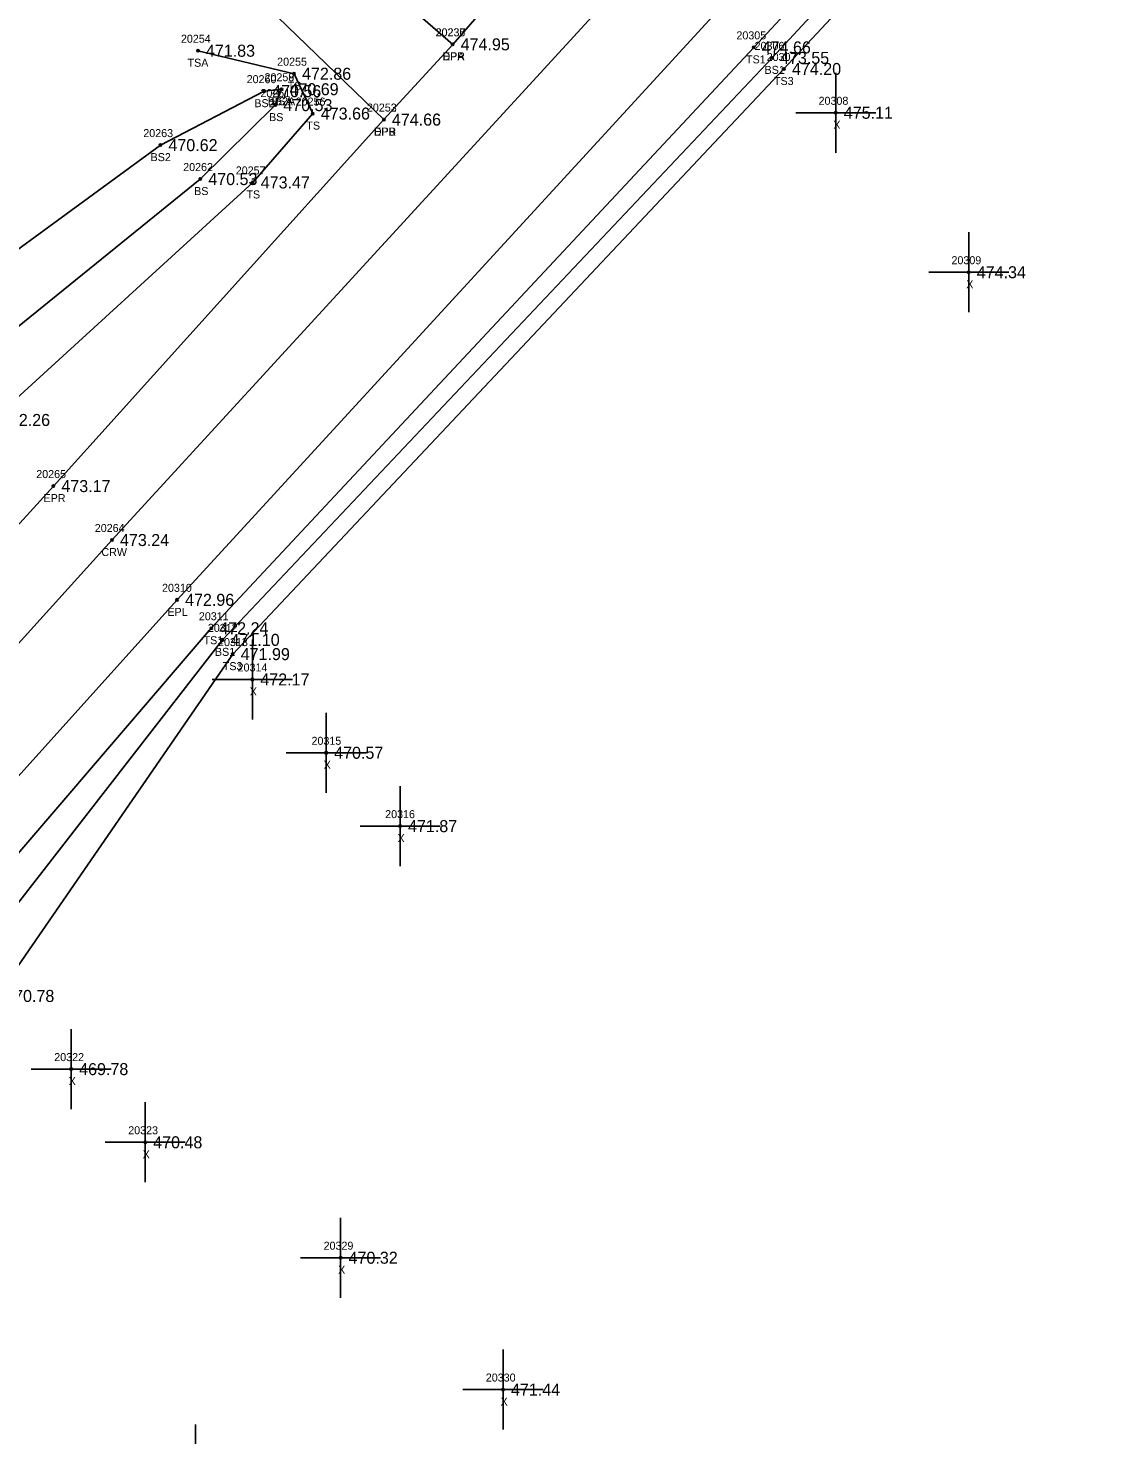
# Model space of a CAD drawing. Extents: x 1741010 to 1742139, y 749382 to 750625.
# Drawn here: x 1741665.8 to 1741801.4, y 750041.3 to 750217 of the extents above; entities that cross this region are included whole.
import ezdxf

# ---------------------------------------------------------------- set-up
doc = ezdxf.new("R2010")
doc.units = 0
for name, color, linetype in [('RD_DTM_BkLn1', 7, 'Continuous'), ('RD_DTM_BkLn2', 7, 'Continuous'), ('RD_DTM_BkLn_txCode', 7, 'Continuous'), ('RD_EX_Driveway', 7, 'Continuous'), ('RD_EX_Driveway_txCode', 7, 'Continuous'), ('RD_EX_Misc', 7, 'Continuous'), ('RD_EX_Misc_txCode', 7, 'Continuous'), ('RD_EX_Road', 7, 'Continuous'), ('RD_EX_Road_txCode', 7, 'Continuous'), ('RD_EX_TX_Driveway_ELEV', 7, 'Continuous'), ('RD_EX_TX_Misc_ELEV', 7, 'Continuous'), ('RD_EX_TX_Road_ELEV', 7, 'Continuous'), ('RD_HC_Survey_ELEV', 7, 'Continuous'), ('RD_HC_Survey_txCode', 7, 'Continuous'), ('RD_SMD_Locator', 7, 'Continuous')]:
    doc.layers.add(name, color=color, linetype=linetype)

msp = doc.modelspace()

# ---------------------------------------------------------------- linework, layer by layer
at = {"layer": 'RD_DTM_BkLn1'}
msp.add_lwpolyline([(1742095.1, 750579.47), (1742056.96, 750547.11), (1742019.74, 750514.22), (1741983.45, 750480.17), (1741948.01, 750445.01), (1741913.15, 750409.3), (1741879.03, 750372.99), (1741811.59, 750300.09), (1741743.65, 750226.52), (1741676.29, 750153.06), (1741642.32, 750115.53), (1741610.32, 750077.63)], dxfattribs=at)
at = {"layer": 'RD_DTM_BkLn2'}
for points in [[(1742105.6, 750567.48), (1742094.25, 750560.49), (1742091.64, 750555.7), (1742067.93, 750534.94), (1742031.73, 750501.95), (1741994.85, 750467.63), (1741959.82, 750432.06), (1741925.8, 750396.31), (1741891.25, 750362.62), (1741824.36, 750287.7), (1741756.44, 750214.6), (1741688.69, 750142.04), (1741655.55, 750103.43), (1741644.64, 750083.31), (1741626.06, 750060.3), (1741620, 750055.3), (1741614.97, 750059.12), (1741617.5, 750064.27), (1741619.23, 750067.96)], [(1742107.37, 750564.98), (1742099.21, 750558.66), (1742095.99, 750559.5), (1742095.15, 750554.39), (1742069.73, 750532.61), (1742034.06, 750499.81), (1741997.6, 750464.99), (1741961.88, 750429.54), (1741928.13, 750394.17), (1741895.34, 750359.02), (1741826.5, 750286.36), (1741758.73, 750213.29), (1741690.1, 750140.59), (1741658.36, 750099.77), (1741650.43, 750077.87), (1741632.9, 750061.59), (1741621.97, 750051.56), (1741618.99, 750048.78), (1741611.88, 750047.79)], [(1742108.6, 750563.87), (1742101.48, 750556.48), (1742102.57, 750548.5), (1742101.05, 750532.99), (1742105.06, 750513.92), (1742103.27, 750510.53), (1742100.54, 750509.6), (1742099.13, 750514.58), (1742095.78, 750530.6), (1742094.19, 750550.08), (1742071, 750531.59), (1742035.26, 750498.87), (1741998.91, 750463.73), (1741964.71, 750427.12), (1741930.26, 750392.09), (1741896.36, 750357.96), (1741828.15, 750284.74), (1741760.22, 750211.9), (1741691.37, 750138.81), (1741661.95, 750096.11), (1741655.14, 750072.69), (1741637.21, 750056.01), (1741627.61, 750046.43), (1741623.09, 750045.5)], [(1741687.02, 750214.18), (1741699.03, 750211.31), (1741701.37, 750206.33), (1741693.87, 750197.73), (1741661.42, 750168.06), (1741625.78, 750132.25), (1741598.95, 750108.26), (1741594.55, 750101.81), (1741595.44, 750091.73), (1741598, 750085.41), (1741619.23, 750067.96)], [(1741697.46, 750209.37), (1741696.69, 750207.39), (1741687.32, 750198.15), (1741655.45, 750172.38), (1741616.11, 750137.65), (1741593.67, 750111.75), (1741586.25, 750102.97)], [(1741697.46, 750209.37), (1741695.29, 750209.13), (1741682.34, 750202.39), (1741649.3, 750178.22), (1741602.32, 750146.46), (1741587.3, 750140.26)]]:
    msp.add_lwpolyline(points, dxfattribs=at)
at = {"layer": 'RD_EX_Driveway'}
msp.add_lwpolyline([(1741718.84, 750214.98), (1741710.44, 750222.3), (1741700.44, 750230.38), (1741692.18, 750223.09), (1741710.25, 750205.58)], dxfattribs=at)
at = {"layer": 'RD_EX_Misc'}
for p, q in [((1741766.69, 750201.43), (1741766.69, 750211.43)), ((1741761.69, 750206.43), (1741771.69, 750206.43)), ((1741783.3, 750181.51), (1741783.3, 750191.51)), ((1741778.3, 750186.51), (1741788.3, 750186.51)), ((1741693.82, 750130.64), (1741693.82, 750140.64)), ((1741688.82, 750135.64), (1741698.82, 750135.64)), ((1741703.04, 750121.48), (1741703.04, 750131.48)), ((1741698.04, 750126.48), (1741708.04, 750126.48)), ((1741712.27, 750112.32), (1741712.27, 750122.32)), ((1741707.27, 750117.32), (1741717.27, 750117.32)), ((1741671.19, 750081.97), (1741671.19, 750091.97)), ((1741666.19, 750086.97), (1741676.19, 750086.97)), ((1741680.44, 750072.83), (1741680.44, 750082.83)), ((1741675.44, 750077.83), (1741685.44, 750077.83)), ((1741704.84, 750058.41), (1741704.84, 750068.41)), ((1741699.84, 750063.41), (1741709.84, 750063.41)), ((1741725.13, 750041.94), (1741725.13, 750051.94)), ((1741720.13, 750046.94), (1741730.13, 750046.94)), ((1741686.74, 750032.59), (1741686.74, 750042.59))]:
    msp.add_line(p, q, dxfattribs=at)
at = {"layer": 'RD_EX_Road'}
for points in [[(1742095.24, 750593.27), (1742088.27, 750587.97), (1742078.23, 750580.89), (1742049.13, 750555.21), (1742012.94, 750522.73), (1741975.54, 750488.03), (1741940.71, 750452.82), (1741916.22, 750428.67), (1741904.72, 750416.99), (1741884.38, 750395.02), (1741870.75, 750380.27), (1741817.36, 750322.98), (1741803.89, 750307.66), (1741783.86, 750287.33), (1741735.44, 750234.07), (1741718.84, 750214.98), (1741710.25, 750205.58), (1741668.97, 750159.8), (1741635, 750122.49), (1741604.35, 750087.7), (1741600.63, 750085.47)], [(1742102.43, 750570.61), (1742093.26, 750562.71), (1742064.72, 750538.42), (1742027.92, 750505.65), (1741991.25, 750471.83), (1741956.32, 750436.98), (1741921.43, 750401.39), (1741886.79, 750364.93), (1741819.64, 750292.67), (1741751.78, 750219.01), (1741684.42, 750145.59), (1741650.98, 750108.5), (1741637.17, 750092.42), (1741621.17, 750073.94), (1741621.31, 750072.22), (1741619.24, 750070.27)]]:
    msp.add_lwpolyline(points, dxfattribs=at)
at = {"layer": 'RD_SMD_Locator'}
for centre in [(1741687.02, 750214.18), (1741718.84, 750214.98), (1741718.84, 750214.98), (1741756.44, 750214.6), (1741758.73, 750213.29), (1741760.22, 750211.9), (1741699.03, 750211.31), (1741695.29, 750209.13), (1741697.46, 750209.37), (1741697.46, 750209.37), (1741696.69, 750207.39), (1741701.37, 750206.33), (1741710.25, 750205.58), (1741710.25, 750205.58), (1741766.69, 750206.43), (1741682.34, 750202.39), (1741687.32, 750198.15), (1741693.87, 750197.73), (1741783.3, 750186.51), (1741668.97, 750159.8), (1741676.29, 750153.06), (1741684.42, 750145.59), (1741688.69, 750142.04), (1741690.1, 750140.59), (1741691.37, 750138.81), (1741693.82, 750135.64), (1741703.04, 750126.48), (1741712.27, 750117.32), (1741671.19, 750086.97), (1741680.44, 750077.83), (1741704.84, 750063.41), (1741725.13, 750046.94)]:
    msp.add_circle(centre, 0.15, dxfattribs=at)

# ---------------------------------------------------------------- texts
at = {"layer": 'RD_DTM_BkLn_txCode'}
for s, p in [('20254', (1741684.9, 750215.18)), ('20305', (1741754.28, 750215.6)), ('20306', (1741756.55, 750214.29)), ('20307', (1741758.06, 750212.9)), ('TSA', (1741685.73, 750212.18)), ('20255', (1741696.92, 750212.31)), ('TS1', (1741755.48, 750212.6)), ('BS1', (1741757.79, 750211.29)), ('20260', (1741693.11, 750210.13)), ('20258', (1741695.34, 750210.37)), ('20259', (1741695.34, 750210.37)), ('TS', (1741698.24, 750209.31)), ('TS3', (1741758.97, 750209.9)), ('20261', (1741694.83, 750208.39)), ('BS2', (1741694.07, 750207.13)), ('BS2A', (1741695.74, 750207.37)), ('BSA', (1741696.19, 750207.37)), ('20256', (1741699.23, 750207.33)), ('BS', (1741695.91, 750205.39)), ('TS', (1741700.57, 750204.33)), ('20263', (1741680.2, 750203.39)), ('BS2', (1741681.11, 750200.39)), ('20262', (1741685.18, 750199.15)), ('20257', (1741691.75, 750198.73)), ('BS', (1741686.55, 750196.15)), ('TS', (1741693.08, 750195.73)), ('20311', (1741687.14, 750143.04)), ('20312', (1741688.26, 750141.59)), ('TS1', (1741687.73, 750140.04)), ('20313', (1741689.54, 750139.81)), ('BS1', (1741689.15, 750138.59)), ('TS3', (1741690.13, 750136.81))]:
    msp.add_text(s, height=1, dxfattribs=at).set_placement(p)
at = {"layer": 'RD_EX_Driveway_txCode'}
for s, p in [('20237', (1741716.72, 750215.98)), ('DPA', (1741717.57, 750212.98)), ('20252', (1741708.13, 750206.58)), ('DPB', (1741708.99, 750203.58))]:
    msp.add_text(s, height=1, dxfattribs=at).set_placement(p)
at = {"layer": 'RD_EX_Misc_txCode'}
for s, p in [('20308', (1741764.54, 750207.43)), ('X', (1741766.38, 750204.43)), ('20309', (1741781.14, 750187.51)), ('X', (1741782.99, 750184.51)), ('20314', (1741691.98, 750136.64)), ('X', (1741693.5, 750133.64)), ('20315', (1741701.21, 750127.48)), ('X', (1741702.73, 750124.48)), ('20316', (1741710.41, 750118.32)), ('X', (1741711.95, 750115.32)), ('20322', (1741669.08, 750087.97)), ('X', (1741670.88, 750084.97)), ('20323', (1741678.32, 750078.83)), ('X', (1741680.12, 750075.83)), ('20329', (1741702.72, 750064.41)), ('X', (1741704.53, 750061.41)), ('20330', (1741722.98, 750047.94)), ('X', (1741724.82, 750044.94))]:
    msp.add_text(s, height=1, dxfattribs=at).set_placement(p)
at = {"layer": 'RD_EX_Road_txCode'}
for s, p in [('20236', (1741716.7, 750215.98)), ('EPR', (1741717.61, 750212.98)), ('20253', (1741708.13, 750206.58)), ('EPR', (1741709.02, 750203.58)), ('20265', (1741666.83, 750160.8)), ('EPR', (1741667.74, 750157.8)), ('20310', (1741682.54, 750146.59)), ('EPL', (1741683.21, 750143.59))]:
    msp.add_text(s, height=1, dxfattribs=at).set_placement(p)
at = {"layer": 'RD_EX_TX_Driveway_ELEV'}
for s, p in [('474.95', (1741719.84, 750214.23)), ('474.66', (1741711.25, 750204.83))]:
    msp.add_text(s, height=1.5, dxfattribs=at).set_placement(p)
at = {"layer": 'RD_EX_TX_Misc_ELEV'}
for s, p in [('471.83', (1741688.02, 750213.43)), ('474.66', (1741757.44, 750213.85)), ('473.55', (1741759.73, 750212.54)), ('472.86', (1741700.03, 750210.56)), ('474.20', (1741761.22, 750211.15)), ('470.56', (1741696.29, 750208.38)), ('470.69', (1741698.46, 750208.62)), ('470.69', (1741698.46, 750208.62)), ('470.53', (1741697.69, 750206.64)), ('473.66', (1741702.37, 750205.58)), ('475.11', (1741767.69, 750205.68)), ('470.62', (1741683.34, 750201.64)), ('470.53', (1741688.32, 750197.4)), ('473.47', (1741694.87, 750196.98)), ('474.34', (1741784.3, 750185.76)), ('472.26', (1741662.42, 750167.31)), ('472.24', (1741689.69, 750141.29)), ('471.10', (1741691.1, 750139.84)), ('471.99', (1741692.37, 750138.06)), ('472.17', (1741694.82, 750134.89)), ('470.57', (1741704.04, 750125.73)), ('471.87', (1741713.27, 750116.57)), ('470.78', (1741662.95, 750095.36)), ('469.78', (1741672.19, 750086.22)), ('470.48', (1741681.44, 750077.08)), ('470.32', (1741705.84, 750062.66)), ('471.44', (1741726.13, 750046.19))]:
    msp.add_text(s, height=1.5, dxfattribs=at).set_placement(p)
at = {"layer": 'RD_EX_TX_Road_ELEV'}
for s, p in [('474.95', (1741719.84, 750214.23)), ('474.66', (1741711.25, 750204.83)), ('473.17', (1741669.97, 750159.05)), ('472.96', (1741685.42, 750144.84))]:
    msp.add_text(s, height=1.5, dxfattribs=at).set_placement(p)
at = {"layer": 'RD_HC_Survey_ELEV'}
msp.add_text('473.24', height=1.5, dxfattribs=at).set_placement((1741677.29, 750152.31))
at = {"layer": 'RD_HC_Survey_txCode'}
for s, p in [('20264', (1741674.14, 750154.06)), ('CRW', (1741674.97, 750151.06))]:
    msp.add_text(s, height=1, dxfattribs=at).set_placement(p)

doc.saveas('drawing.dxf')
